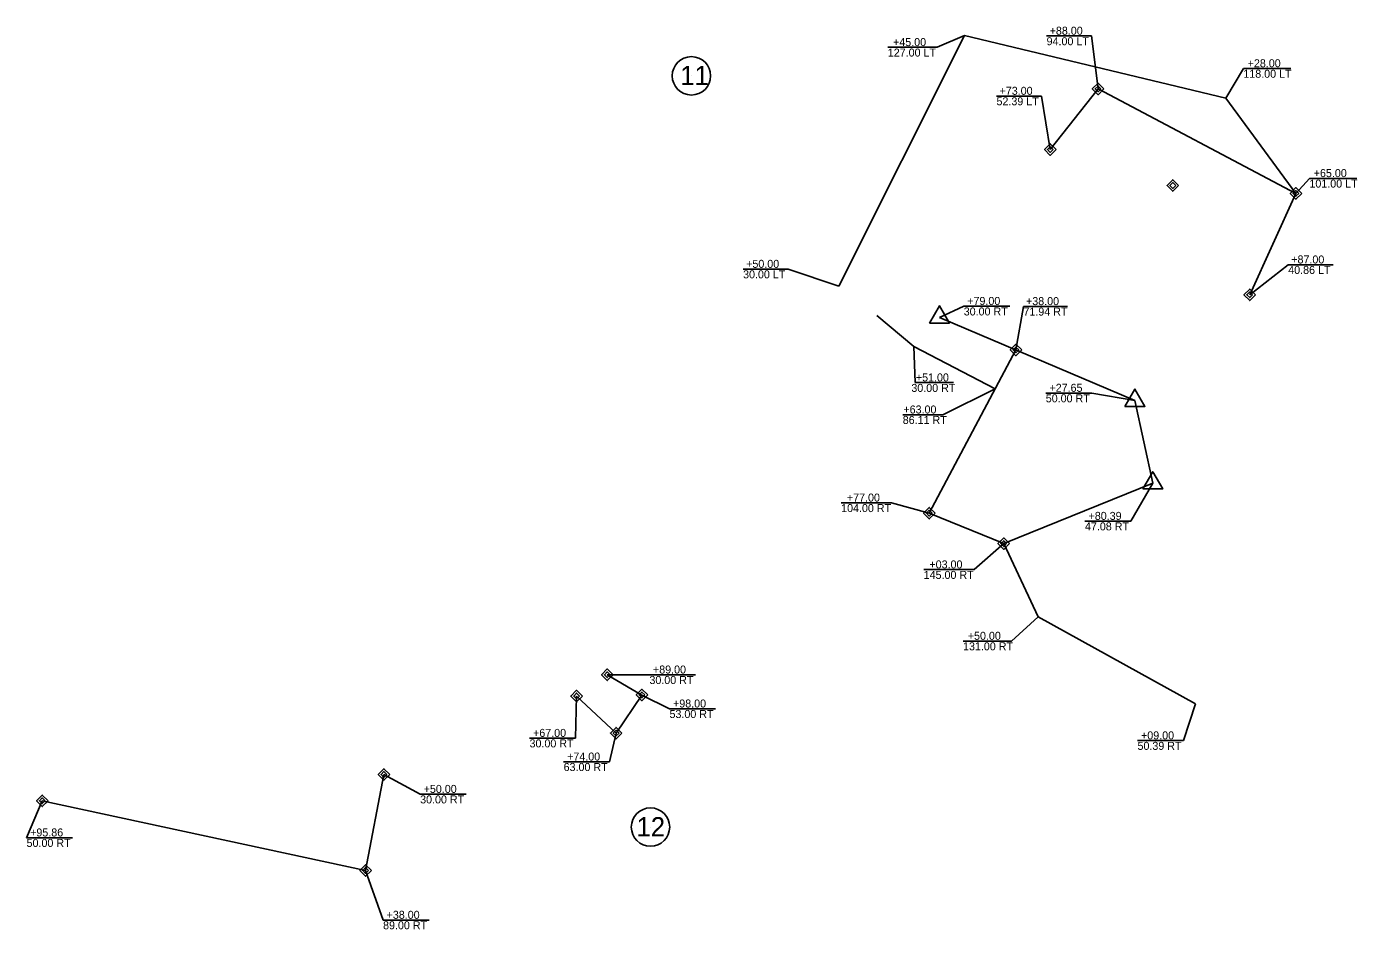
# Model space of a CAD drawing. Extents: x 1002576 to 1014655, y 551673 to 557994.
# Drawn here: x 1005856 to 1006687, y 552125 to 552689 of the extents above; entities that cross this region are included whole.
import ezdxf

# ---------------------------------------------------------------- set-up
doc = ezdxf.new("R2010")
doc.units = 0
for name, color, linetype in [('Exist Building', 7, 'Continuous'), ('Exist DTM Crownline', 7, 'Continuous'), ('Exist Guardrail', 7, 'Continuous'), ('Exist Hydro River Flow Arrow CELL', 7, 'Continuous'), ('Exist Hydro Stream or Body of Water', 7, 'Continuous'), ('Exist Other Culture Area Outline', 7, 'Continuous'), ('Exist Other Culture Fence Line', 7, 'Continuous'), ('Exist Roads EOP Other', 7, 'Continuous'), ('Exist Roads EOP Text', 7, 'Continuous'), ('Exist Roads Soil', 7, 'Continuous'), ('Exist Roads Soil Text', 7, 'Continuous'), ('Exist Structure Major Deck Tunnel Box Culvert', 7, 'Continuous'), ('Exist Utilities Power Pole CELL', 7, 'Continuous'), ('Exist Vegetation Woods Line', 7, 'Continuous')]:
    doc.layers.add(name, color=color, linetype=linetype)

msp = doc.modelspace()

# ---------------------------------------------------------------- linework, layer by layer
at = {"layer": 'Exist Building'}
for p, q in [((1006419.99, 552385.26), (1006474.14, 552487.24)), ((1006466.46, 552366.25), (1006559.6, 552404)), ((1006420.01, 552385.28), (1006466.46, 552366.25)), ((1006218.88, 552284.35), (1006240.4, 552271.66)), ((1006199.69, 552271.06), (1006224.42, 552247.91)), ((1006224.42, 552247.91), (1006240.4, 552271.66))]:
    msp.add_line(p, q, dxfattribs=at)
at = {"layer": 'Exist DTM Crownline'}
msp.add_line((1006387.29, 552508.66), (1006410.37, 552489.49), dxfattribs=at)
at = {"layer": 'Exist Guardrail'}
for p, q in [((1006363.57, 552527.06), (1006441.95, 552683.66)), ((1006441.95, 552683.66), (1006605.25, 552644.49)), ((1006605.25, 552644.49), (1006649.03, 552585.01)), ((1006410.37, 552489.49), (1006461.2, 552462.87)), ((1006466.46, 552366.25), (1006487.94, 552320.63)), ((1006487.94, 552320.63), (1006586.37, 552266.13))]:
    msp.add_line(p, q, dxfattribs=at)
at = {"layer": 'Exist Hydro River Flow Arrow CELL'}
for p, q in [((1006470.24, 552514.56), (1006441.54, 552514.56)), ((1006521.48, 552460.31), (1006492.78, 552460.31)), ((1006545.96, 552380.3), (1006517.25, 552380.3))]:
    msp.add_line(p, q, dxfattribs=at)
for points in [[(1006441.54, 552514.56), (1006426.32, 552507.6)], [(1006521.48, 552460.31), (1006548.42, 552455.61)], [(1006545.96, 552380.3), (1006559.6, 552404)]]:
    msp.add_lwpolyline(points, dxfattribs=at)
at = {"layer": 'Exist Hydro Stream or Body of Water'}
for p, q in [((1006525.4, 552650.28), (1006525.4, 552650.28)), ((1006495.58, 552612.39), (1006495.58, 552612.39)), ((1006572.1, 552589.96), (1006572.1, 552589.96)), ((1006649.03, 552585.01), (1006649.03, 552585.01)), ((1006620.13, 552521.69), (1006620.13, 552521.69)), ((1006426.33, 552507.61), (1006426.33, 552507.61)), ((1006474.14, 552487.24), (1006474.14, 552487.24)), ((1006548.42, 552455.61), (1006548.42, 552455.61)), ((1006559.6, 552404), (1006559.6, 552404)), ((1006420.01, 552385.28), (1006420.01, 552385.28)), ((1006466.46, 552366.25), (1006466.46, 552366.25)), ((1006218.88, 552284.35), (1006218.88, 552284.35)), ((1006199.69, 552271.06), (1006199.69, 552271.06)), ((1006240.55, 552271.71), (1006240.55, 552271.71)), ((1006224.42, 552247.91), (1006224.42, 552247.91)), ((1006079.39, 552222.04), (1006079.39, 552222.04)), ((1005865.98, 552205.64), (1005865.98, 552205.64)), ((1006067.94, 552162.06), (1006067.94, 552162.06))]:
    msp.add_line(p, q, dxfattribs=at)
for points in [[(1006420.08, 552504.01), (1006426.33, 552514.81), (1006432.58, 552504.01)], [(1006542.17, 552452.01), (1006548.42, 552462.81), (1006554.67, 552452.01)], [(1006553.35, 552400.4), (1006559.6, 552411.2), (1006565.85, 552400.4)]]:
    msp.add_lwpolyline(points, close=True, dxfattribs=at)
at = {"layer": 'Exist Other Culture Area Outline'}
for p, q in [((1006067.94, 552162.06), (1006079.39, 552222.04)), ((1005865.98, 552205.64), (1006067.94, 552162.06))]:
    msp.add_line(p, q, dxfattribs=at)
at = {"layer": 'Exist Other Culture Fence Line'}
for p, q in [((1006521.42, 552683.34), (1006493.3, 552683.34)), ((1006490.12, 552645.83), (1006462, 552645.83)), ((1006687.14, 552594.42), (1006657.46, 552594.42)), ((1006672.33, 552540.49), (1006644.22, 552540.49))]:
    msp.add_line(p, q, dxfattribs=at)
for points in [[(1006521.42, 552683.34), (1006525.4, 552650.28)], [(1006490.12, 552645.83), (1006495.58, 552612.39)], [(1006657.46, 552594.42), (1006649.03, 552585.01)], [(1006644.22, 552540.49), (1006620.13, 552521.69)]]:
    msp.add_lwpolyline(points, dxfattribs=at)
at = {"layer": 'Exist Roads EOP Other'}
for p, q in [((1006130.71, 552209.77), (1006102, 552209.77)), ((1005884.89, 552182.58), (1005856.18, 552182.58)), ((1006107.56, 552131.16), (1006078.85, 552131.16))]:
    msp.add_line(p, q, dxfattribs=at)
for points in [[(1006102, 552209.77), (1006079.39, 552222.04)], [(1005856.18, 552182.58), (1005865.98, 552205.64)], [(1006078.85, 552131.16), (1006067.94, 552162.06)]]:
    msp.add_lwpolyline(points, dxfattribs=at)
at = {"layer": 'Exist Roads EOP Text'}
for p, q in [((1006506.34, 552514.47), (1006478.83, 552514.47)), ((1006396.43, 552391.74), (1006364.97, 552391.74)), ((1006447.98, 552350), (1006416.52, 552350)), ((1006273.93, 552284.35), (1006245.22, 552284.35)), ((1006286.46, 552263.12), (1006257.76, 552263.12)), ((1006199.04, 552244.77), (1006170.33, 552244.77)), ((1006220.32, 552230), (1006191.62, 552230))]:
    msp.add_line(p, q, dxfattribs=at)
for points in [[(1006478.83, 552514.47), (1006474.14, 552487.24)], [(1006396.43, 552391.74), (1006420.01, 552385.28)], [(1006447.98, 552350), (1006466.46, 552366.25)], [(1006245.22, 552284.35), (1006218.88, 552284.35)], [(1006199.04, 552244.77), (1006199.69, 552271.06)], [(1006257.76, 552263.12), (1006240.4, 552271.66)], [(1006220.32, 552230), (1006224.42, 552247.91)]]:
    msp.add_lwpolyline(points, dxfattribs=at)
at = {"layer": 'Exist Roads Soil'}
for p, q in [((1006426.32, 552507.6), (1006548.42, 552455.61)), ((1006548.42, 552455.61), (1006559.6, 552404))]:
    msp.add_line(p, q, dxfattribs=at)
at = {"layer": 'Exist Roads Soil Text'}
for p, q in [((1006424.98, 552676.26), (1006394.11, 552676.26)), ((1006645.87, 552663.03), (1006616.19, 552663.03)), ((1006331.84, 552537.74), (1006303.73, 552537.74)), ((1006435.2, 552466.8), (1006411.15, 552466.8)), ((1006428.56, 552446.78), (1006403.44, 552446.78)), ((1006471.36, 552305.41), (1006441.09, 552305.41)), ((1006578.78, 552243.22), (1006550.07, 552243.22))]:
    msp.add_line(p, q, dxfattribs=at)
for points in [[(1006424.98, 552676.26), (1006441.95, 552683.66)], [(1006616.19, 552663.03), (1006605.25, 552644.49)], [(1006331.84, 552537.74), (1006363.57, 552527.06)], [(1006411.15, 552466.8), (1006410.37, 552489.48)], [(1006428.56, 552446.78), (1006461.2, 552462.87)], [(1006471.36, 552305.41), (1006487.94, 552320.63)], [(1006578.78, 552243.22), (1006586.37, 552266.13)]]:
    msp.add_lwpolyline(points, dxfattribs=at)
at = {"layer": 'Exist Structure Major Deck Tunnel Box Culvert'}
for points in [[(1006529, 552650.28), (1006525.4, 552646.68), (1006521.8, 552650.28), (1006525.4, 552653.88)], [(1006527.2, 552650.28), (1006525.4, 552648.48), (1006523.6, 552650.28), (1006525.4, 552652.08)], [(1006499.18, 552612.39), (1006495.58, 552608.79), (1006491.98, 552612.39), (1006495.58, 552615.99)], [(1006497.38, 552612.39), (1006495.58, 552610.59), (1006493.78, 552612.39), (1006495.58, 552614.19)], [(1006575.7, 552589.96), (1006572.1, 552586.36), (1006568.5, 552589.96), (1006572.1, 552593.56)], [(1006573.9, 552589.96), (1006572.1, 552588.16), (1006570.3, 552589.96), (1006572.1, 552591.76)], [(1006652.63, 552585.01), (1006649.03, 552581.41), (1006645.43, 552585.01), (1006649.03, 552588.61)], [(1006650.83, 552585.01), (1006649.03, 552583.21), (1006647.23, 552585.01), (1006649.03, 552586.81)], [(1006623.73, 552521.69), (1006620.13, 552518.09), (1006616.53, 552521.69), (1006620.13, 552525.29)], [(1006621.93, 552521.69), (1006620.13, 552519.89), (1006618.33, 552521.69), (1006620.13, 552523.49)], [(1006477.74, 552487.24), (1006474.14, 552483.64), (1006470.54, 552487.24), (1006474.14, 552490.84)], [(1006475.94, 552487.24), (1006474.14, 552485.44), (1006472.34, 552487.24), (1006474.14, 552489.04)], [(1006423.61, 552385.28), (1006420.01, 552381.68), (1006416.41, 552385.28), (1006420.01, 552388.88)], [(1006421.81, 552385.28), (1006420.01, 552383.48), (1006418.21, 552385.28), (1006420.01, 552387.08)], [(1006470.06, 552366.25), (1006466.46, 552362.65), (1006462.86, 552366.25), (1006466.46, 552369.85)], [(1006468.26, 552366.25), (1006466.46, 552364.45), (1006464.66, 552366.25), (1006466.46, 552368.05)], [(1006222.48, 552284.35), (1006218.88, 552280.75), (1006215.28, 552284.35), (1006218.88, 552287.95)], [(1006220.68, 552284.35), (1006218.88, 552282.55), (1006217.08, 552284.35), (1006218.88, 552286.15)], [(1006203.29, 552271.06), (1006199.69, 552267.46), (1006196.09, 552271.06), (1006199.69, 552274.66)], [(1006201.49, 552271.06), (1006199.69, 552269.26), (1006197.89, 552271.06), (1006199.69, 552272.86)], [(1006244.15, 552271.71), (1006240.55, 552268.11), (1006236.95, 552271.71), (1006240.55, 552275.31)], [(1006242.35, 552271.71), (1006240.55, 552269.91), (1006238.75, 552271.71), (1006240.55, 552273.51)], [(1006228.02, 552247.91), (1006224.42, 552244.31), (1006220.82, 552247.91), (1006224.42, 552251.51)], [(1006226.22, 552247.91), (1006224.42, 552246.11), (1006222.62, 552247.91), (1006224.42, 552249.71)], [(1006082.99, 552222.04), (1006079.39, 552218.44), (1006075.79, 552222.04), (1006079.39, 552225.64)], [(1006081.19, 552222.04), (1006079.39, 552220.24), (1006077.59, 552222.04), (1006079.39, 552223.84)], [(1005869.58, 552205.64), (1005865.98, 552202.04), (1005862.38, 552205.64), (1005865.98, 552209.24)], [(1005867.78, 552205.64), (1005865.98, 552203.84), (1005864.18, 552205.64), (1005865.98, 552207.44)], [(1006071.54, 552162.06), (1006067.94, 552158.46), (1006064.34, 552162.06), (1006067.94, 552165.66)], [(1006069.74, 552162.06), (1006067.94, 552160.26), (1006066.14, 552162.06), (1006067.94, 552163.86)]]:
    msp.add_lwpolyline(points, close=True, dxfattribs=at)
at = {"layer": 'Exist Utilities Power Pole CELL'}
for p, q in [((1006271.44, 552658.45), (1006271.44, 552658.45)), ((1006245.87, 552189.21), (1006245.87, 552189.21))]:
    msp.add_line(p, q, dxfattribs=at)
for centre in [(1006271.44, 552658.45), (1006245.87, 552189.21)]:
    msp.add_circle(centre, 12, dxfattribs=at)
at = {"layer": 'Exist Vegetation Woods Line'}
for p, q in [((1006495.58, 552612.39), (1006525.4, 552650.28)), ((1006525.4, 552650.28), (1006649.03, 552585.01)), ((1006620.13, 552521.69), (1006649.03, 552585.01))]:
    msp.add_line(p, q, dxfattribs=at)

# ---------------------------------------------------------------- texts
at = {"layer": 'Exist Hydro River Flow Arrow CELL'}
for s, p in [('+79.00', (1006443.72, 552515.34)), ('30.00 RT', (1006441.51, 552508.78)), ('50.00 RT', (1006492.76, 552454.53)), ('+27.65', (1006495.06, 552461.08)), ('+80.39', (1006519.48, 552381.08)), ('47.08 RT', (1006517.23, 552374.53))]:
    msp.add_text(s, height=5, dxfattribs=at).set_placement(p)
at = {"layer": 'Exist Other Culture Fence Line'}
for s, p in [('+88.00', (1006495.19, 552684.12)), ('94.00 LT', (1006493.28, 552677.56)), ('+73.00', (1006463.89, 552646.6)), ('52.39 LT', (1006461.98, 552640.05)), ('+65.00', (1006660.13, 552595.19)), ('101.00 LT', (1006657.44, 552588.64)), ('+87.00', (1006646.1, 552541.27)), ('40.86 LT', (1006644.2, 552534.71))]:
    msp.add_text(s, height=5, dxfattribs=at).set_placement(p)
at = {"layer": 'Exist Roads EOP Other'}
for s, p in [('+50.00', (1006104.18, 552210.55)), ('30.00 RT', (1006101.98, 552203.99)), ('+95.86', (1005858.38, 552183.35)), ('50.00 RT', (1005856.16, 552176.8)), ('+38.00', (1006081.03, 552131.93)), ('89.00 RT', (1006078.83, 552125.38))]:
    msp.add_text(s, height=5, dxfattribs=at).set_placement(p)
at = {"layer": 'Exist Roads EOP Text'}
for s, p in [('+38.00', (1006480.42, 552515.24)), ('71.94 RT', (1006478.81, 552508.69)), ('+77.00', (1006368.53, 552392.52)), ('104.00 RT', (1006364.94, 552385.97)), ('+03.00', (1006420.08, 552350.78)), ('145.00 RT', (1006416.5, 552344.23)), ('+89.00', (1006247.41, 552285.12)), ('30.00 RT', (1006245.2, 552278.57)), ('+98.00', (1006259.94, 552263.9)), ('53.00 RT', (1006257.74, 552257.34)), ('30.00 RT', (1006170.31, 552238.99)), ('+67.00', (1006172.51, 552245.54)), ('+74.00', (1006193.8, 552230.77)), ('63.00 RT', (1006191.6, 552224.22))]:
    msp.add_text(s, height=5, dxfattribs=at).set_placement(p)
at = {"layer": 'Exist Roads Soil Text'}
for s, p in [('127.00 LT', (1006394.09, 552670.48)), ('+45.00', (1006397.37, 552677.03)), ('+28.00', (1006618.86, 552663.81)), ('118.00 LT', (1006616.17, 552657.25)), ('+50.00', (1006305.61, 552538.52)), ('30.00 LT', (1006303.7, 552531.97)), ('+51.00', (1006411.61, 552467.58)), ('30.00 RT', (1006408.8, 552461.02)), ('+63.00', (1006403.83, 552447.55)), ('86.11 RT', (1006403.42, 552441)), ('+50.00', (1006444.05, 552306.19)), ('131.00 RT', (1006441.07, 552299.63)), ('+09.00', (1006552.26, 552243.99)), ('50.39 RT', (1006550.05, 552237.44))]:
    msp.add_text(s, height=5, dxfattribs=at).set_placement(p)
at = {"layer": 'Exist Utilities Power Pole CELL'}
for s, p in [('11', (1006264.43, 552652.67)), ('12', (1006237.14, 552183.43))]:
    msp.add_text(s, height=12, dxfattribs=at).set_placement(p)

doc.saveas('drawing.dxf')
